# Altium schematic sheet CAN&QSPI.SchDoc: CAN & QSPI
size A4; DocumentNumber: MB1165; Revision: C.1; SheetNumber: 11; SheetTotal: 17; Project: STM32469I-EVAL
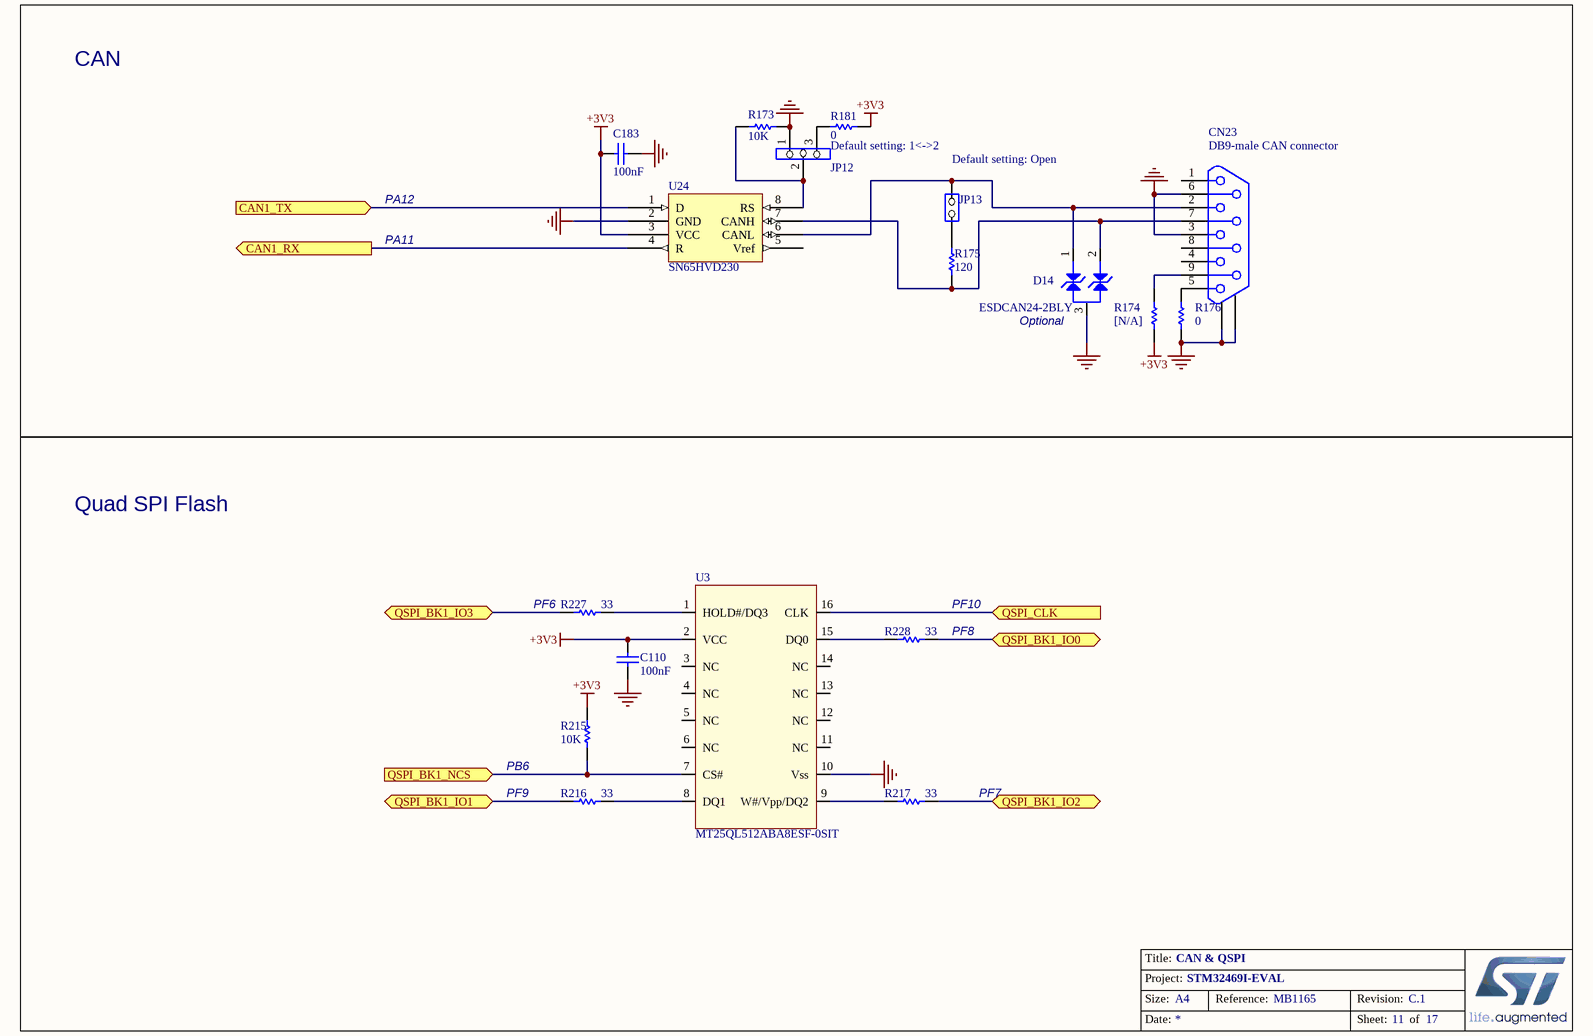
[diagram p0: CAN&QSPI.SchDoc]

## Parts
C110  100nF  [0402C]
C183  100nF  [0603C]
CN23  DB9-male CAN connector  [DB9/M]
D14  ESDCAN24-2BLY  [SOT-23]
JP12  (no value)  [SIP3]
JP13  (no value)  [SIP2]
R173  10K  [0603R]
R174  [N/A]  [0603R]
R175  120  [0603R]
R176  0  [0603R]
R181  0  [0603R]
R215  10K  [0402R]
R216  33  [0603R]
R217  33  [0603R]
R227  33  [0603R]
R228  33  [0603R]
U3  MT25QL512ABA8ESF-0SIT  [SOIC16W_1R27_10R3X10R33]
U24  SN65HVD230  [SOIC8_1R27_4R9X6]

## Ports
CAN1_RX (out), CAN1_TX (in), QSPI_BK1_IO0 (bidir), QSPI_BK1_IO1 (bidir), QSPI_BK1_IO2 (bidir), QSPI_BK1_IO3 (bidir), QSPI_BK1_NCS (in), QSPI_CLK (in)

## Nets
+3V3: C110.1 C183.1 R174.1 R181.2 R215.1 U3.2(VCC) U24.3(VCC)
GND: C110.2 C183.2 CN23.3 CN23.6 CN23.10 CN23.11 D14.3 JP12.1 R173.2 R176.1 U3.10(Vss) U24.2(GND)
CAN1_RX: U24.4(R) ; port CAN1_RX
CAN1_TX: U24.1(D) ; port CAN1_TX
QSPI_BK1_IO0: R228.1 ; port QSPI_BK1_IO0
QSPI_BK1_IO1: R216.2 ; port QSPI_BK1_IO1
QSPI_BK1_IO2: R217.1 ; port QSPI_BK1_IO2
QSPI_BK1_IO3: R227.2 ; port QSPI_BK1_IO3
QSPI_BK1_NCS: R215.2 U3.7(CS#) ; port QSPI_BK1_NCS
QSPI_CLK: U3.16(CLK) ; port QSPI_CLK
NetCN23_2: CN23.2 D14.1 JP13.2(NO) U24.6(CANL)
NetCN23_5: CN23.5 R176.2
NetCN23_7: CN23.7 D14.2 R175.1 U24.7(CANH)
NetCN23_9: CN23.9 R174.2
NetJP12_2: JP12.2 R173.1 U24.8(RS)
NetJP12_3: JP12.3 R181.1
NetJP13_1: JP13.1(COMMON) R175.2
NetR216_1: R216.1 U3.8(DQ1)
NetR217_2: R217.2 U3.9(W#/Vpp/DQ2)
NetR227_1: R227.1 U3.1(HOLD#/DQ3)
NetR228_2: R228.2 U3.15(DQ0)

Not connected (* = marked no-connect by the designer): CN23 1 4 8; U3 3(NC) 4(NC) 5(NC) 6(NC) 11(NC) 12(NC) 13(NC) 14(NC); U24 5(Vref)

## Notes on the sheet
- CAN
- Default setting: 1<->2
- (near JP13) Default setting: Open
- PA12
- PA11
- (near D14) Optional
- Quad SPI Flash
- (near R227) PF6
- (near R228) PF8
- (near R228) PF10
- PB6
- PF9
- (near R217) PF7

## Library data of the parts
C110 = Cap: Capacitor; Value: 10nF; Ordered by: Subcon
C183 = Cap: Capacitor; Value: 10nF
CN23 = DB9-CAN
JP12 = Jumper3
JP13 = JP2
R173 R216 R217 R227 R228 = Res1: Resistor; Value: 1K
R174-R176 R181 = res1: Resistor; Value: 1K
R215 = res1: Resistor; Value: 1K; Ordered by: Subcon
U3 = QSPI_16pins: ECCN_US/EU: 3A991
U24 = SN65HVD230D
